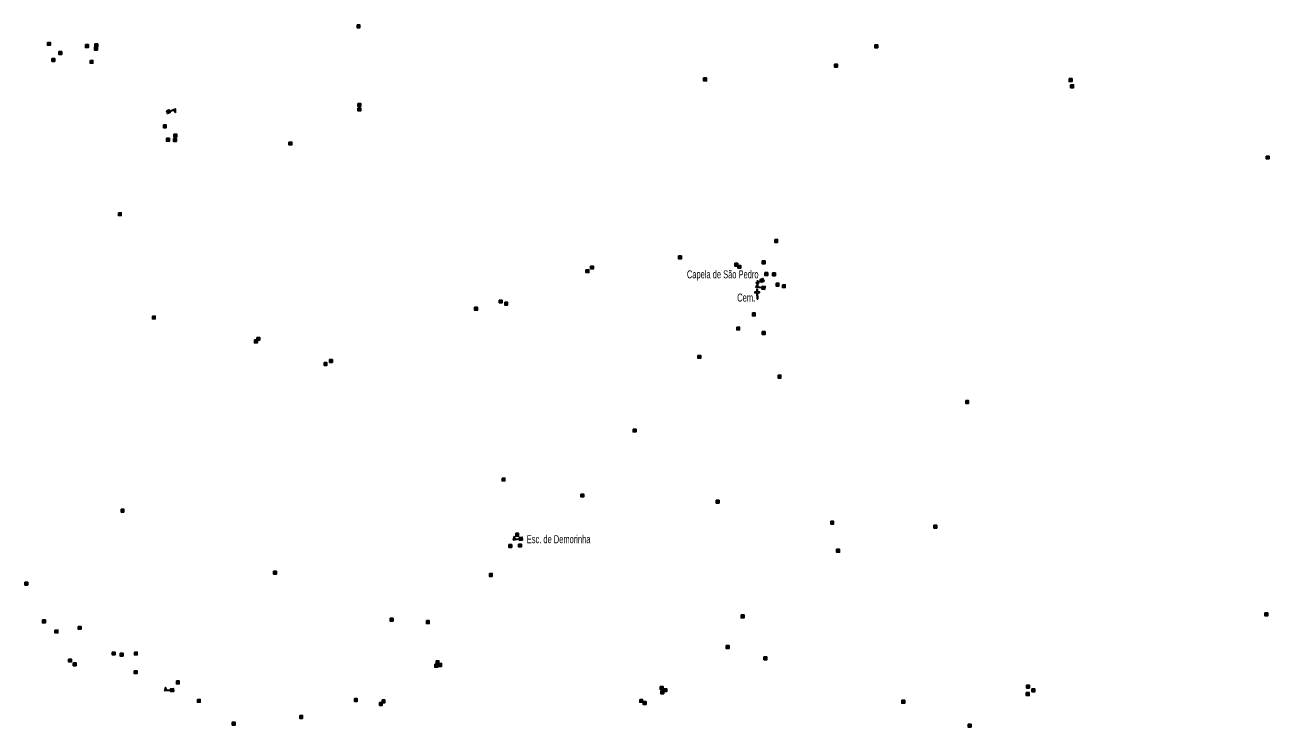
# Model space of a CAD drawing. Extents: x 647.8 to 672.9, y 6929.3 to 6957.3.
# Drawn here: x 660.12 to 672.56, y 6936.24 to 6943.26 of the extents above; entities that cross this region are included whole.
import ezdxf
from ezdxf.enums import TextEntityAlignment as Align

# ---------------------------------------------------------------- set-up
doc = ezdxf.new("R2010")
doc.units = 0
doc.header["$LTSCALE"] = 0.032
for name, color, linetype, lineweight in [('2', 7, 'Continuous', 25), ('20', 7, 'Continuous', 25), ('4', 7, 'Continuous', 25), ('6', 7, 'Continuous', 25)]:
    doc.layers.add(name, color=color, linetype=linetype, lineweight=lineweight)
doc.layers.add('61', color=7, linetype='Continuous')

msp = doc.modelspace()

# ---------------------------------------------------------------- hatches: boundary and pattern name
at = {"layer": '2'}
for points in [[(663.4398, 6943.2575), (663.4688, 6943.2575), (663.4688, 6943.2285), (663.4398, 6943.2285)], [(660.3465, 6943.082), (660.3755, 6943.082), (660.3755, 6943.053), (660.3465, 6943.053)], [(660.4606, 6942.9899), (660.4896, 6942.9899), (660.4896, 6942.9609), (660.4606, 6942.9609)], [(660.726, 6943.0601), (660.755, 6943.0601), (660.755, 6943.0311), (660.726, 6943.0311)], [(660.816, 6943.0337), (660.845, 6943.0337), (660.845, 6943.0047), (660.816, 6943.0047)], [(660.8204, 6943.0666), (660.8494, 6943.0666), (660.8494, 6943.0376), (660.8204, 6943.0376)], [(668.6151, 6943.0579), (668.6441, 6943.0579), (668.6441, 6943.0289), (668.6151, 6943.0289)], [(660.3904, 6942.9219), (660.4194, 6942.9219), (660.4194, 6942.8929), (660.3904, 6942.8929)], [(660.7721, 6942.9021), (660.8011, 6942.9021), (660.8011, 6942.8731), (660.7721, 6942.8731)], [(668.2114, 6942.8648), (668.2404, 6942.8648), (668.2404, 6942.8358), (668.2114, 6942.8358)], [(666.9039, 6942.7266), (666.9329, 6942.7266), (666.9329, 6942.6976), (666.9039, 6942.6976)], [(670.5567, 6942.72), (670.5857, 6942.72), (670.5857, 6942.691), (670.5567, 6942.691)], [(670.572, 6942.6586), (670.601, 6942.6586), (670.601, 6942.6296), (670.572, 6942.6296)], [(663.4486, 6942.4721), (663.4776, 6942.4721), (663.4776, 6942.4431), (663.4486, 6942.4431)], [(663.4486, 6942.426), (663.4776, 6942.426), (663.4776, 6942.397), (663.4486, 6942.397)], [(661.5047, 6942.2581), (661.5337, 6942.2581), (661.5337, 6942.2291), (661.5047, 6942.2291)], [(661.5356, 6942.1233), (661.5646, 6942.1233), (661.5646, 6942.0943), (661.5356, 6942.0943)], [(661.6058, 6942.1211), (661.6348, 6942.1211), (661.6348, 6942.0921), (661.6058, 6942.0921)], [(661.6101, 6942.165), (661.6391, 6942.165), (661.6391, 6942.136), (661.6101, 6942.136)], [(662.7597, 6942.086), (662.7887, 6942.086), (662.7887, 6942.057), (662.7597, 6942.057)], [(672.5267, 6941.9456), (672.5557, 6941.9456), (672.5557, 6941.9166), (672.5267, 6941.9166)], [(661.0551, 6941.3796), (661.0841, 6941.3796), (661.0841, 6941.3506), (661.0551, 6941.3506)], [(667.6147, 6941.1119), (667.6437, 6941.1119), (667.6437, 6941.0829), (667.6147, 6941.0829)], [(665.7741, 6940.8465), (665.8031, 6940.8465), (665.8031, 6940.8175), (665.7741, 6940.8175)], [(666.6538, 6940.9474), (666.6828, 6940.9474), (666.6828, 6940.9184), (666.6538, 6940.9184)], [(667.2154, 6940.875), (667.2444, 6940.875), (667.2444, 6940.846), (667.2154, 6940.846)], [(667.2461, 6940.8531), (667.2751, 6940.8531), (667.2751, 6940.8241), (667.2461, 6940.8241)], [(667.4897, 6940.8969), (667.5187, 6940.8969), (667.5187, 6940.8679), (667.4897, 6940.8679)], [(665.728, 6940.8092), (665.757, 6940.8092), (665.757, 6940.7802), (665.728, 6940.7802)], [(667.516, 6940.7807), (667.545, 6940.7807), (667.545, 6940.7517), (667.516, 6940.7517)], [(667.5928, 6940.7785), (667.6218, 6940.7785), (667.6218, 6940.7495), (667.5928, 6940.7495)], [(667.6279, 6940.6754), (667.6569, 6940.6754), (667.6569, 6940.6464), (667.6279, 6940.6464)], [(667.6915, 6940.66), (667.7205, 6940.66), (667.7205, 6940.631), (667.6915, 6940.631)], [(664.8614, 6940.5064), (664.8904, 6940.5064), (664.8904, 6940.4774), (664.8614, 6940.4774)], [(664.9163, 6940.4845), (664.9453, 6940.4845), (664.9453, 6940.4555), (664.9163, 6940.4555)], [(661.3951, 6940.3463), (661.4241, 6940.3463), (661.4241, 6940.3173), (661.3951, 6940.3173)], [(664.6157, 6940.434), (664.6447, 6940.434), (664.6447, 6940.405), (664.6157, 6940.405)], [(667.3909, 6940.377), (667.4199, 6940.377), (667.4199, 6940.348), (667.3909, 6940.348)], [(667.2352, 6940.2366), (667.2642, 6940.2366), (667.2642, 6940.2076), (667.2352, 6940.2076)], [(662.4153, 6940.1071), (662.4443, 6940.1071), (662.4443, 6940.0781), (662.4153, 6940.0781)], [(662.4394, 6940.1335), (662.4684, 6940.1335), (662.4684, 6940.1045), (662.4394, 6940.1045)], [(667.4897, 6940.1905), (667.5187, 6940.1905), (667.5187, 6940.1615), (667.4897, 6940.1615)], [(663.1107, 6939.8812), (663.1397, 6939.8812), (663.1397, 6939.8522), (663.1107, 6939.8522)], [(663.1656, 6939.9119), (663.1946, 6939.9119), (663.1946, 6939.8829), (663.1656, 6939.8829)], [(666.8469, 6939.9536), (666.8759, 6939.9536), (666.8759, 6939.9246), (666.8469, 6939.9246)], [(667.6476, 6939.7561), (667.6766, 6939.7561), (667.6766, 6939.7271), (667.6476, 6939.7271)], [(669.5233, 6939.5016), (669.5523, 6939.5016), (669.5523, 6939.4726), (669.5233, 6939.4726)], [(666.1997, 6939.2164), (666.2287, 6939.2164), (666.2287, 6939.1874), (666.1997, 6939.1874)], [(664.8899, 6938.7272), (664.9189, 6938.7272), (664.9189, 6938.6982), (664.8899, 6938.6982)], [(665.6775, 6938.5671), (665.7065, 6938.5671), (665.7065, 6938.5381), (665.6775, 6938.5381)], [(667.0289, 6938.5056), (667.0579, 6938.5056), (667.0579, 6938.4766), (667.0289, 6938.4766)], [(661.0814, 6938.4157), (661.1104, 6938.4157), (661.1104, 6938.3867), (661.0814, 6938.3867)], [(668.1741, 6938.295), (668.2031, 6938.295), (668.2031, 6938.266), (668.1741, 6938.266)], [(669.2052, 6938.2555), (669.2342, 6938.2555), (669.2342, 6938.2265), (669.2052, 6938.2265)], [(665.026, 6938.1744), (665.055, 6938.1744), (665.055, 6938.1454), (665.026, 6938.1454)], [(664.958, 6938.0625), (664.987, 6938.0625), (664.987, 6938.0335), (664.958, 6938.0335)], [(665.0545, 6938.0669), (665.0835, 6938.0669), (665.0835, 6938.0379), (665.0545, 6938.0379)], [(668.2334, 6938.0142), (668.2624, 6938.0142), (668.2624, 6937.9852), (668.2334, 6937.9852)], [(662.6062, 6937.7948), (662.6352, 6937.7948), (662.6352, 6937.7658), (662.6062, 6937.7658)], [(664.7627, 6937.7729), (664.7917, 6937.7729), (664.7917, 6937.7439), (664.7627, 6937.7439)], [(660.1205, 6937.6851), (660.1495, 6937.6851), (660.1495, 6937.6561), (660.1205, 6937.6561)], [(667.279, 6937.3583), (667.308, 6937.3583), (667.308, 6937.3293), (667.279, 6937.3293)], [(672.5136, 6937.378), (672.5426, 6937.378), (672.5426, 6937.349), (672.5136, 6937.349)], [(660.296, 6937.3078), (660.325, 6937.3078), (660.325, 6937.2788), (660.296, 6937.2788)], [(660.6536, 6937.2442), (660.6826, 6937.2442), (660.6826, 6937.2152), (660.6536, 6937.2152)], [(663.7711, 6937.3253), (663.8001, 6937.3253), (663.8001, 6937.2963), (663.7711, 6937.2963)], [(664.1331, 6937.3012), (664.1621, 6937.3012), (664.1621, 6937.2722), (664.1331, 6937.2722)], [(660.4211, 6937.2069), (660.4501, 6937.2069), (660.4501, 6937.1779), (660.4211, 6937.1779)], [(660.9937, 6936.9875), (661.0227, 6936.9875), (661.0227, 6936.9585), (660.9937, 6936.9585)], [(661.0727, 6936.9765), (661.1017, 6936.9765), (661.1017, 6936.9475), (661.0727, 6936.9475)], [(661.2153, 6936.9875), (661.2443, 6936.9875), (661.2443, 6936.9585), (661.2153, 6936.9585)], [(667.1299, 6937.0511), (667.1589, 6937.0511), (667.1589, 6937.0221), (667.1299, 6937.0221)], [(660.5571, 6936.9173), (660.5861, 6936.9173), (660.5861, 6936.8883), (660.5571, 6936.8883)], [(660.6032, 6936.88), (660.6322, 6936.88), (660.6322, 6936.851), (660.6032, 6936.851)], [(664.2164, 6936.8646), (664.2454, 6936.8646), (664.2454, 6936.8356), (664.2164, 6936.8356)], [(664.2296, 6936.8997), (664.2586, 6936.8997), (664.2586, 6936.8707), (664.2296, 6936.8707)], [(664.2559, 6936.8734), (664.2849, 6936.8734), (664.2849, 6936.8444), (664.2559, 6936.8444)], [(667.5072, 6936.9392), (667.5362, 6936.9392), (667.5362, 6936.9102), (667.5072, 6936.9102)], [(661.2131, 6936.801), (661.2421, 6936.801), (661.2421, 6936.772), (661.2131, 6936.772)], [(661.6343, 6936.6979), (661.6633, 6936.6979), (661.6633, 6936.6689), (661.6343, 6936.6689)], [(666.4695, 6936.6431), (666.4985, 6936.6431), (666.4985, 6936.6141), (666.4695, 6936.6141)], [(666.5068, 6936.6211), (666.5358, 6936.6211), (666.5358, 6936.5921), (666.5068, 6936.5921)], [(670.131, 6936.6562), (670.16, 6936.6562), (670.16, 6936.6272), (670.131, 6936.6272)], [(670.1859, 6936.6189), (670.2149, 6936.6189), (670.2149, 6936.5899), (670.1859, 6936.5899)], [(661.8449, 6936.5136), (661.8739, 6936.5136), (661.8739, 6936.4846), (661.8449, 6936.4846)], [(663.4135, 6936.5224), (663.4425, 6936.5224), (663.4425, 6936.4934), (663.4135, 6936.4934)], [(663.6636, 6936.4829), (663.6926, 6936.4829), (663.6926, 6936.4539), (663.6636, 6936.4539)], [(663.6899, 6936.5092), (663.7189, 6936.5092), (663.7189, 6936.4802), (663.6899, 6936.4802)], [(666.2655, 6936.5136), (666.2945, 6936.5136), (666.2945, 6936.4846), (666.2655, 6936.4846)], [(666.3006, 6936.4917), (666.3296, 6936.4917), (666.3296, 6936.4627), (666.3006, 6936.4627)], [(666.4761, 6936.5992), (666.5051, 6936.5992), (666.5051, 6936.5702), (666.4761, 6936.5702)], [(668.8849, 6936.5049), (668.9139, 6936.5049), (668.9139, 6936.4759), (668.8849, 6936.4759)], [(670.1289, 6936.5816), (670.1579, 6936.5816), (670.1579, 6936.5526), (670.1289, 6936.5526)], [(662.1937, 6936.2855), (662.2227, 6936.2855), (662.2227, 6936.2565), (662.1937, 6936.2565)], [(662.8672, 6936.3535), (662.8962, 6936.3535), (662.8962, 6936.3245), (662.8672, 6936.3245)], [(669.5475, 6936.2657), (669.5765, 6936.2657), (669.5765, 6936.2367), (669.5475, 6936.2367)]]:
    msp.add_hatch(color=256, dxfattribs=at).paths.add_polyline_path(points)
at = {"layer": '4'}
for points in [[(661.5354, 6942.3981), (661.5637, 6942.4082), (661.5737, 6942.3799), (661.5455, 6942.3699)], [(667.5163, 6940.613), (667.4865, 6940.616), (667.4895, 6940.6458), (667.5193, 6940.6428)], [(665.0947, 6938.1061), (665.065, 6938.1021), (665.061, 6938.1318), (665.0907, 6938.1359)], [(661.6092, 6936.5925), (661.5793, 6936.5904), (661.5772, 6936.6203), (661.6071, 6936.6224)]]:
    msp.add_hatch(color=256, dxfattribs=at).paths.add_polyline_path(points)
at = {"layer": '6'}
for points in [[(667.4806, 6940.6832), (667.5081, 6940.6951), (667.4962, 6940.7226), (667.4687, 6940.7108)], [(667.4737, 6940.6993), (667.4756, 6940.6947), (667.4504, 6940.6838), (667.4553, 6940.6723), (667.4508, 6940.6704), (667.4458, 6940.6818), (667.4298, 6940.6749), (667.4278, 6940.6795), (667.4439, 6940.6865), (667.4388, 6940.6979), (667.4435, 6940.6998), (667.4484, 6940.6884)]]:
    msp.add_hatch(color=256, dxfattribs=at).paths.add_polyline_path(points)

# ---------------------------------------------------------------- linework, layer by layer
at = {"layer": '2'}
for points in [[(663.4398, 6943.2575), (663.4688, 6943.2575), (663.4688, 6943.2285), (663.4398, 6943.2285)], [(660.3465, 6943.082), (660.3755, 6943.082), (660.3755, 6943.053), (660.3465, 6943.053)], [(660.4606, 6942.9899), (660.4896, 6942.9899), (660.4896, 6942.9609), (660.4606, 6942.9609)], [(660.726, 6943.0601), (660.755, 6943.0601), (660.755, 6943.0311), (660.726, 6943.0311)], [(660.816, 6943.0337), (660.845, 6943.0337), (660.845, 6943.0047), (660.816, 6943.0047)], [(660.8204, 6943.0666), (660.8494, 6943.0666), (660.8494, 6943.0376), (660.8204, 6943.0376)], [(668.6151, 6943.0579), (668.6441, 6943.0579), (668.6441, 6943.0289), (668.6151, 6943.0289)], [(660.3904, 6942.9219), (660.4194, 6942.9219), (660.4194, 6942.8929), (660.3904, 6942.8929)], [(660.7721, 6942.9021), (660.8011, 6942.9021), (660.8011, 6942.8731), (660.7721, 6942.8731)], [(668.2114, 6942.8648), (668.2404, 6942.8648), (668.2404, 6942.8358), (668.2114, 6942.8358)], [(666.9039, 6942.7266), (666.9329, 6942.7266), (666.9329, 6942.6976), (666.9039, 6942.6976)], [(670.5567, 6942.72), (670.5857, 6942.72), (670.5857, 6942.691), (670.5567, 6942.691)], [(670.572, 6942.6586), (670.601, 6942.6586), (670.601, 6942.6296), (670.572, 6942.6296)], [(663.4486, 6942.4721), (663.4776, 6942.4721), (663.4776, 6942.4431), (663.4486, 6942.4431)], [(663.4486, 6942.426), (663.4776, 6942.426), (663.4776, 6942.397), (663.4486, 6942.397)], [(661.5047, 6942.2581), (661.5337, 6942.2581), (661.5337, 6942.2291), (661.5047, 6942.2291)], [(661.5356, 6942.1233), (661.5646, 6942.1233), (661.5646, 6942.0943), (661.5356, 6942.0943)], [(661.6058, 6942.1211), (661.6348, 6942.1211), (661.6348, 6942.0921), (661.6058, 6942.0921)], [(661.6101, 6942.165), (661.6391, 6942.165), (661.6391, 6942.136), (661.6101, 6942.136)], [(662.7597, 6942.086), (662.7887, 6942.086), (662.7887, 6942.057), (662.7597, 6942.057)], [(672.5267, 6941.9456), (672.5557, 6941.9456), (672.5557, 6941.9166), (672.5267, 6941.9166)], [(661.0551, 6941.3796), (661.0841, 6941.3796), (661.0841, 6941.3506), (661.0551, 6941.3506)], [(667.6147, 6941.1119), (667.6437, 6941.1119), (667.6437, 6941.0829), (667.6147, 6941.0829)], [(665.7741, 6940.8465), (665.8031, 6940.8465), (665.8031, 6940.8175), (665.7741, 6940.8175)], [(666.6538, 6940.9474), (666.6828, 6940.9474), (666.6828, 6940.9184), (666.6538, 6940.9184)], [(667.2154, 6940.875), (667.2444, 6940.875), (667.2444, 6940.846), (667.2154, 6940.846)], [(667.2461, 6940.8531), (667.2751, 6940.8531), (667.2751, 6940.8241), (667.2461, 6940.8241)], [(667.4897, 6940.8969), (667.5187, 6940.8969), (667.5187, 6940.8679), (667.4897, 6940.8679)], [(665.728, 6940.8092), (665.757, 6940.8092), (665.757, 6940.7802), (665.728, 6940.7802)], [(667.516, 6940.7807), (667.545, 6940.7807), (667.545, 6940.7517), (667.516, 6940.7517)], [(667.5928, 6940.7785), (667.6218, 6940.7785), (667.6218, 6940.7495), (667.5928, 6940.7495)], [(667.6279, 6940.6754), (667.6569, 6940.6754), (667.6569, 6940.6464), (667.6279, 6940.6464)], [(667.6915, 6940.66), (667.7205, 6940.66), (667.7205, 6940.631), (667.6915, 6940.631)], [(664.8614, 6940.5064), (664.8904, 6940.5064), (664.8904, 6940.4774), (664.8614, 6940.4774)], [(664.9163, 6940.4845), (664.9453, 6940.4845), (664.9453, 6940.4555), (664.9163, 6940.4555)], [(661.3951, 6940.3463), (661.4241, 6940.3463), (661.4241, 6940.3173), (661.3951, 6940.3173)], [(664.6157, 6940.434), (664.6447, 6940.434), (664.6447, 6940.405), (664.6157, 6940.405)], [(667.3909, 6940.377), (667.4199, 6940.377), (667.4199, 6940.348), (667.3909, 6940.348)], [(667.2352, 6940.2366), (667.2642, 6940.2366), (667.2642, 6940.2076), (667.2352, 6940.2076)], [(662.4153, 6940.1071), (662.4443, 6940.1071), (662.4443, 6940.0781), (662.4153, 6940.0781)], [(662.4394, 6940.1335), (662.4684, 6940.1335), (662.4684, 6940.1045), (662.4394, 6940.1045)], [(667.4897, 6940.1905), (667.5187, 6940.1905), (667.5187, 6940.1615), (667.4897, 6940.1615)], [(663.1107, 6939.8812), (663.1397, 6939.8812), (663.1397, 6939.8522), (663.1107, 6939.8522)], [(663.1656, 6939.9119), (663.1946, 6939.9119), (663.1946, 6939.8829), (663.1656, 6939.8829)], [(666.8469, 6939.9536), (666.8759, 6939.9536), (666.8759, 6939.9246), (666.8469, 6939.9246)], [(667.6476, 6939.7561), (667.6766, 6939.7561), (667.6766, 6939.7271), (667.6476, 6939.7271)], [(669.5233, 6939.5016), (669.5523, 6939.5016), (669.5523, 6939.4726), (669.5233, 6939.4726)], [(666.1997, 6939.2164), (666.2287, 6939.2164), (666.2287, 6939.1874), (666.1997, 6939.1874)], [(664.8899, 6938.7272), (664.9189, 6938.7272), (664.9189, 6938.6982), (664.8899, 6938.6982)], [(665.6775, 6938.5671), (665.7065, 6938.5671), (665.7065, 6938.5381), (665.6775, 6938.5381)], [(667.0289, 6938.5056), (667.0579, 6938.5056), (667.0579, 6938.4766), (667.0289, 6938.4766)], [(661.0814, 6938.4157), (661.1104, 6938.4157), (661.1104, 6938.3867), (661.0814, 6938.3867)], [(668.1741, 6938.295), (668.2031, 6938.295), (668.2031, 6938.266), (668.1741, 6938.266)], [(669.2052, 6938.2555), (669.2342, 6938.2555), (669.2342, 6938.2265), (669.2052, 6938.2265)], [(665.026, 6938.1744), (665.055, 6938.1744), (665.055, 6938.1454), (665.026, 6938.1454)], [(664.958, 6938.0625), (664.987, 6938.0625), (664.987, 6938.0335), (664.958, 6938.0335)], [(665.0545, 6938.0669), (665.0835, 6938.0669), (665.0835, 6938.0379), (665.0545, 6938.0379)], [(668.2334, 6938.0142), (668.2624, 6938.0142), (668.2624, 6937.9852), (668.2334, 6937.9852)], [(662.6062, 6937.7948), (662.6352, 6937.7948), (662.6352, 6937.7658), (662.6062, 6937.7658)], [(664.7627, 6937.7729), (664.7917, 6937.7729), (664.7917, 6937.7439), (664.7627, 6937.7439)], [(660.1205, 6937.6851), (660.1495, 6937.6851), (660.1495, 6937.6561), (660.1205, 6937.6561)], [(667.279, 6937.3583), (667.308, 6937.3583), (667.308, 6937.3293), (667.279, 6937.3293)], [(672.5136, 6937.378), (672.5426, 6937.378), (672.5426, 6937.349), (672.5136, 6937.349)], [(660.296, 6937.3078), (660.325, 6937.3078), (660.325, 6937.2788), (660.296, 6937.2788)], [(660.6536, 6937.2442), (660.6826, 6937.2442), (660.6826, 6937.2152), (660.6536, 6937.2152)], [(663.7711, 6937.3253), (663.8001, 6937.3253), (663.8001, 6937.2963), (663.7711, 6937.2963)], [(664.1331, 6937.3012), (664.1621, 6937.3012), (664.1621, 6937.2722), (664.1331, 6937.2722)], [(660.4211, 6937.2069), (660.4501, 6937.2069), (660.4501, 6937.1779), (660.4211, 6937.1779)], [(660.9937, 6936.9875), (661.0227, 6936.9875), (661.0227, 6936.9585), (660.9937, 6936.9585)], [(661.0727, 6936.9765), (661.1017, 6936.9765), (661.1017, 6936.9475), (661.0727, 6936.9475)], [(661.2153, 6936.9875), (661.2443, 6936.9875), (661.2443, 6936.9585), (661.2153, 6936.9585)], [(667.1299, 6937.0511), (667.1589, 6937.0511), (667.1589, 6937.0221), (667.1299, 6937.0221)], [(660.5571, 6936.9173), (660.5861, 6936.9173), (660.5861, 6936.8883), (660.5571, 6936.8883)], [(660.6032, 6936.88), (660.6322, 6936.88), (660.6322, 6936.851), (660.6032, 6936.851)], [(664.2164, 6936.8646), (664.2454, 6936.8646), (664.2454, 6936.8356), (664.2164, 6936.8356)], [(664.2296, 6936.8997), (664.2586, 6936.8997), (664.2586, 6936.8707), (664.2296, 6936.8707)], [(664.2559, 6936.8734), (664.2849, 6936.8734), (664.2849, 6936.8444), (664.2559, 6936.8444)], [(667.5072, 6936.9392), (667.5362, 6936.9392), (667.5362, 6936.9102), (667.5072, 6936.9102)], [(661.2131, 6936.801), (661.2421, 6936.801), (661.2421, 6936.772), (661.2131, 6936.772)], [(661.6343, 6936.6979), (661.6633, 6936.6979), (661.6633, 6936.6689), (661.6343, 6936.6689)], [(666.4695, 6936.6431), (666.4985, 6936.6431), (666.4985, 6936.6141), (666.4695, 6936.6141)], [(666.5068, 6936.6211), (666.5358, 6936.6211), (666.5358, 6936.5921), (666.5068, 6936.5921)], [(670.131, 6936.6562), (670.16, 6936.6562), (670.16, 6936.6272), (670.131, 6936.6272)], [(670.1859, 6936.6189), (670.2149, 6936.6189), (670.2149, 6936.5899), (670.1859, 6936.5899)], [(661.8449, 6936.5136), (661.8739, 6936.5136), (661.8739, 6936.4846), (661.8449, 6936.4846)], [(663.4135, 6936.5224), (663.4425, 6936.5224), (663.4425, 6936.4934), (663.4135, 6936.4934)], [(663.6636, 6936.4829), (663.6926, 6936.4829), (663.6926, 6936.4539), (663.6636, 6936.4539)], [(663.6899, 6936.5092), (663.7189, 6936.5092), (663.7189, 6936.4802), (663.6899, 6936.4802)], [(666.2655, 6936.5136), (666.2945, 6936.5136), (666.2945, 6936.4846), (666.2655, 6936.4846)], [(666.3006, 6936.4917), (666.3296, 6936.4917), (666.3296, 6936.4627), (666.3006, 6936.4627)], [(666.4761, 6936.5992), (666.5051, 6936.5992), (666.5051, 6936.5702), (666.4761, 6936.5702)], [(668.8849, 6936.5049), (668.9139, 6936.5049), (668.9139, 6936.4759), (668.8849, 6936.4759)], [(670.1289, 6936.5816), (670.1579, 6936.5816), (670.1579, 6936.5526), (670.1289, 6936.5526)], [(662.1937, 6936.2855), (662.2227, 6936.2855), (662.2227, 6936.2565), (662.1937, 6936.2565)], [(662.8672, 6936.3535), (662.8962, 6936.3535), (662.8962, 6936.3245), (662.8672, 6936.3245)], [(669.5475, 6936.2657), (669.5765, 6936.2657), (669.5765, 6936.2367), (669.5475, 6936.2367)]]:
    msp.add_lwpolyline(points, close=True, dxfattribs=at)
at = {"layer": '20'}
for points in [[(667.4354, 6940.5875), (667.4154, 6940.5869), (667.4157, 6940.5784), (667.4357, 6940.579), (667.4376, 6940.5155)], [(667.4434, 6940.5877), (667.4426, 6940.6157), (667.4346, 6940.6155), (667.4354, 6940.5875)], [(667.4437, 6940.5792), (667.4637, 6940.5798), (667.4634, 6940.5883), (667.4434, 6940.5877)], [(667.4376, 6940.5155), (667.4456, 6940.5157), (667.4437, 6940.5792)]]:
    msp.add_lwpolyline(points, dxfattribs=at)
at = {"layer": '4'}
for p, q in [((661.5679, 6942.3964), (661.5695, 6942.3917)), ((667.4877, 6940.6284), (667.4882, 6940.6334)), ((665.0634, 6938.1146), (665.0626, 6938.1195)), ((661.5784, 6936.6029), (661.578, 6936.6079))]:
    msp.add_line(p, q, dxfattribs=at)
for points in [[(661.5354, 6942.3981), (661.5637, 6942.4082), (661.5737, 6942.3799), (661.5455, 6942.3699)], [(661.5679, 6942.3964), (661.6267, 6942.4174), (661.6267, 6942.3802), (661.6067, 6942.405), (661.5695, 6942.3917)], [(667.4877, 6940.6284), (667.4255, 6940.6346), (667.4414, 6940.6682), (667.4489, 6940.6373), (667.4882, 6940.6334)], [(667.5163, 6940.613), (667.4865, 6940.616), (667.4895, 6940.6458), (667.5193, 6940.6428)], [(665.0634, 6938.1146), (665.0014, 6938.1061), (665.0091, 6938.1425), (665.0235, 6938.1142), (665.0626, 6938.1195)], [(665.0947, 6938.1061), (665.065, 6938.1021), (665.061, 6938.1318), (665.0907, 6938.1359)], [(661.5784, 6936.6029), (661.516, 6936.5985), (661.5261, 6936.6343), (661.5386, 6936.6051), (661.578, 6936.6079)], [(661.6092, 6936.5925), (661.5793, 6936.5904), (661.5772, 6936.6203), (661.6071, 6936.6224)]]:
    msp.add_lwpolyline(points, close=True, dxfattribs=at)
at = {"layer": '6'}
for points in [[(667.4806, 6940.6832), (667.5081, 6940.6951), (667.4962, 6940.7226), (667.4687, 6940.7108)], [(667.4737, 6940.6993), (667.4756, 6940.6947), (667.4504, 6940.6838), (667.4553, 6940.6723), (667.4508, 6940.6704), (667.4458, 6940.6818), (667.4298, 6940.6749), (667.4278, 6940.6795), (667.4439, 6940.6865), (667.4388, 6940.6979), (667.4435, 6940.6998), (667.4484, 6940.6884)]]:
    msp.add_lwpolyline(points, close=True, dxfattribs=at)

# ---------------------------------------------------------------- texts
at = {"layer": '61'}
for s, width, p in [('Capela de São Pedro', 0.7, (667.453, 6940.7236)), ('Cem.', 0.65, (667.4198, 6940.4911))]:
    msp.add_text(s, height=0.08, dxfattribs=dict(at, width=width)).set_placement(p, align=Align.RIGHT)
at = {"layer": '61', "width": 0.7}
msp.add_text('Esc. de Demorinha', height=0.08, dxfattribs=at).set_placement((665.1364, 6938.0756))

doc.saveas('drawing.dxf')
